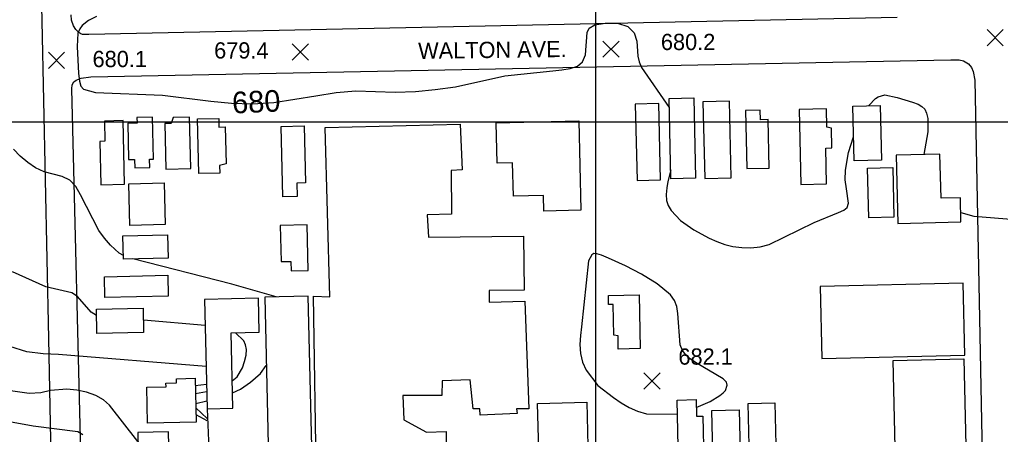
# Model space of a CAD drawing. Extents: x 79600 to 91800, y 75600 to 84400.
# Drawn here: x 81468 to 82374, y 78712 to 79095 of the extents above; entities that cross this region are included whole.
import ezdxf

# ---------------------------------------------------------------- set-up
doc = ezdxf.new("R2010")
doc.units = 0
for name, color, linetype in [('080-085$0$BLDG', 7, 'Continuous'), ('080-085$0$GRID', 7, 'Continuous'), ('080-085$0$INDEX', 7, 'Continuous'), ('080-085$0$INDXLBL', 7, 'Continuous'), ('080-085$0$INTER', 7, 'Continuous'), ('080-085$0$ROAD', 7, 'Continuous'), ('080-085$0$ROAD-NAME', 7, 'Continuous'), ('080-085$0$SPOTMARK', 7, 'Continuous'), ('080-085$0$SPOTS', 7, 'Continuous'), ('080-085$0$WALL', 7, 'Continuous')]:
    doc.layers.add(name, color=color, linetype=linetype)

# ---------------------------------------------------------------- blocks, each defined once
blk = doc.blocks.new('080-085$0$SPOTS')
at = {"layer": '080-085$0$SPOTMARK'}
for p, q in [((-0.5, -0.5), (0.5, 0.5)), ((-0.5, 0.5), (0.5, -0.5))]:
    blk.add_line(p, q, dxfattribs=at)

msp = doc.modelspace()

# ---------------------------------------------------------------- linework, layer by layer
at = {"layer": '080-085$0$BLDG'}
for points in [[(82090.51, 79022.53), (82092.23, 78948.5), (82069.5, 78947.97), (82067.78, 79022)], [(82036.53, 79016.75), (82038.17, 78946.35), (82059.99, 78946.86), (82058.36, 79017.26)], [(82099.04, 79018.93), (82100.68, 78948.3), (82125.11, 78948.87), (82123.47, 79019.5)], [(82213.18, 78943.28), (82212.42, 78976.21), (82218.08, 78976.34), (82217.65, 78994.55), (82213.4, 78995.56), (82213.01, 79012.54), (82187.74, 79011.95), (82189.35, 78942.72)], [(82238.59, 78964.59), (82237.42, 79015.04), (82262.6, 79015.62), (82263.77, 78965.18)], [(81576.7, 78999.36), (81568.13, 78999.16), (81568.91, 78965.57), (81574.34, 78965.69), (81574.52, 78958.04), (81588.4, 78958.36), (81588.22, 78965.98), (81591.91, 78966.06), (81591.01, 79004.77), (81576.58, 79004.44)], [(81608.22, 78998.95), (81602.39, 78998.81), (81603.37, 78956.86), (81626.23, 78957.39), (81625.13, 79004.7), (81610.04, 79004.35)], [(81652.1, 79003.64), (81652.28, 78995.64), (81658.12, 78995.77), (81658.91, 78961.84), (81652.82, 78960.13), (81652.99, 78953.13), (81633.8, 78952.69), (81632.63, 79003.19)], [(82159.1, 79002.61), (82152.15, 79002.45), (82151.95, 79011.15), (82138.39, 79010.84), (82139.63, 78957.32), (82160.14, 78957.79)], [(81546.5, 79001.21), (81546.93, 78982.5), (81542.32, 78982.39), (81543.25, 78942.29), (81565.1, 78942.8), (81563.73, 79001.61)], [(81730.84, 78996.65), (81732.06, 78944.04), (81724.27, 78943.86), (81724.56, 78931.47), (81711.16, 78931.16), (81709.65, 78996.16)], [(81952.12, 78918.06), (81951.79, 78932.47), (81924.11, 78931.83), (81923.39, 78962.71), (81908.97, 78962.37), (81908.11, 78999.64), (81984.31, 79001.41), (81986.23, 78918.85)], [(82336.68, 78930.36), (82318.76, 78929.94), (82317.81, 78970.71), (82277.35, 78969.77), (82278.81, 78906.67), (82337.2, 78908.03)], [(82252.13, 78911.83), (82251.06, 78957.83), (82274.18, 78958.37), (82275.25, 78912.37)], [(81570.08, 78904.84), (81569.18, 78943.29), (81601.7, 78944.05), (81602.59, 78905.6)], [(81708.93, 78904.77), (81709.71, 78871.43), (81718.78, 78871.64), (81718.99, 78862.97), (81734.65, 78863.33), (81733.68, 78905.34)], [(81605.32, 78874.69), (81564.17, 78873.73), (81563.67, 78895.25), (81604.82, 78896.2)], [(81605.54, 78839.62), (81547.08, 78838.27), (81546.63, 78857.53), (81605.09, 78858.89)], [(82208.68, 78781.92), (82340.86, 78785), (82339.32, 78851.44), (82207.14, 78848.36)], [(82020.91, 78790.72), (82020.62, 78803.02), (82016.87, 78803.68), (82016.22, 78831.96), (82011.92, 78831.86), (82011.73, 78840.05), (82040.02, 78840.7), (82041.17, 78791.19)], [(81665.19, 78736.17), (81663.58, 78805.74), (81689.45, 78806.35), (81688.72, 78837.74), (81638.93, 78836.58), (81641.27, 78735.62)], [(81734.68, 78839.52), (81694.54, 78838.59), (81698.65, 78661.69), (81738.79, 78662.62)], [(81582.78, 78806.05), (81539.68, 78805.05), (81539.16, 78827.59), (81582.25, 78828.59)], [(82274.47, 78780.31), (82339.93, 78781.83), (82342.42, 78674.58), (82276.96, 78673.06)], [(81603.44, 78755.91), (81603.36, 78759.27), (81613.12, 78759.49), (81613.03, 78763.35), (81630.31, 78763.75), (81631.25, 78723.35), (81586.41, 78722.31), (81585.64, 78755.49)], [(81946.46, 78740.52), (81991.78, 78741.57), (81993.03, 78687.64), (81947.71, 78686.59)], [(82092.68, 78744.09), (82093.04, 78728.69), (82098.82, 78728.82), (82099.8, 78686.83), (82076.46, 78686.29), (82075.12, 78743.68)], [(82165.37, 78740.96), (82166.56, 78689.53), (82141.99, 78688.95), (82140.8, 78740.39)], [(82132.43, 78734.73), (82133.64, 78682.46), (82108.46, 78681.88), (82107.25, 78734.15)], [(81577.29, 78713.71), (81578.44, 78664.11), (81606.89, 78664.77), (81605.74, 78714.37)]]:
    msp.add_lwpolyline(points, close=True, dxfattribs=at)
msp.add_lwpolyline([(81742.38, 78663.46), (81739.5, 78839.69), (81754.65, 78838.94), (81750.32, 78995.26), (81874.78, 78998.42), (81876.63, 78956.04), (81866.52, 78955.65), (81866.83, 78915.24), (81844.52, 78914.74), (81845.73, 78894.11), (81933.42, 78894.85), (81933.98, 78845.18), (81901.85, 78844.85), (81901.68, 78833.9), (81934.51, 78834.79), (81938.45, 78735.59), (81926.94, 78735.62), (81927.49, 78731.27), (81893.25, 78729.68), (81892.99, 78735.43), (81886.81, 78735.59), (81884.22, 78762.4), (81858.4, 78761.35), (81858.09, 78747.88), (81821.89, 78747.84), (81822.81, 78725.53), (81843.82, 78713.96), (81861.92, 78714.61), (81862.49, 78666.21)], dxfattribs=at)
at = {"layer": '080-085$0$GRID'}
for p, q in [((82000, 80000), (82000, 76000)), ((85000, 79000), (80000, 79000))]:
    msp.add_line(p, q, dxfattribs=at)
at = {"layer": '080-085$0$INDEX'}
for p, q in [((81630.85, 78740.46), (81641.1, 78742.95)), ((81641.53, 78726.51), (81630.95, 78736.44))]:
    msp.add_line(p, q, dxfattribs=at)
for points in [[(81539.12, 79097.8), (81531.83, 79093.98), (81526.12, 79089.4), (81523.78, 79086.42), (81522.18, 79082.37), (81521.51, 79070.03), (81522.62, 79044.95), (81523.42, 79037.98), (81524.83, 79033.31), (81527.4, 79030.51), (81538.34, 79027.64), (81600.29, 79025.07), (81644.92, 79019.65), (81663.72, 79017.64), (81683.15, 79017.22), (81702.82, 79018.35), (81741.65, 79024.35), (81760.41, 79027.56), (81778.61, 79029.17), (81814.84, 79027.92), (81833.57, 79028.36), (81852, 79030.2), (81870.52, 79032.69), (81916.24, 79043.03), (81960.4, 79047.61), (81968.87, 79048.46), (81976.61, 79049.66), (81983.12, 79051.9), (81987.85, 79055.98), (81990.47, 79062.33), (81992.06, 79082.78), (81994.02, 79086.96), (81999.31, 79089.87), (82008.81, 79091.57), (82020.06, 79091.4), (82029.76, 79088.52), (82035.44, 79082.52), (82037.86, 79074.79), (82039.03, 79061.04), (82040.03, 79055.83), (82042.25, 79050.53), (82067.97, 79013.66)], [(82252.24, 79015.38), (82258.26, 79021.88), (82260.78, 79023.67), (82266.91, 79025.24), (82278.41, 79023.05), (82292.56, 79018.62), (82297.64, 79016.67), (82301.19, 79014.66), (82303.69, 79012.05), (82305.51, 79008.39), (82306.66, 79003.63), (82306.6, 78991.08), (82302.86, 78970.36)], [(82069.31, 78956.26), (82066.76, 78945.41), (82065.59, 78939.41), (82064.96, 78933.33), (82065.34, 78927.92), (82066.85, 78923.1), (82069.54, 78918.53), (82078.34, 78909.44), (82090.61, 78900.72), (82104.65, 78893.1), (82111.79, 78889.96), (82119.09, 78887.39), (82126.75, 78885.48), (82134.9, 78884.34), (82143.36, 78884.14), (82151.84, 78885.1), (82160.14, 78887.32), (82201.62, 78907.59), (82224.23, 78916.66), (82229.09, 78918.83), (82232.12, 78921.41), (82233.29, 78925.29), (82231.39, 78938.52), (82230.39, 78947.01), (82230.6, 78955.98), (82233.37, 78972.22), (82238.08, 78986.63)], [(82337, 78916.64), (82348.93, 78913.54), (82398.5, 78909.24), (82416.01, 78908.45), (82456.76, 78912.78), (82495.76, 78914.01), (82513.74, 78915.35), (82523.1, 78916.77), (82532.3, 78919), (82549.37, 78926.02), (82577.6, 78942.02), (82591.27, 78948.92), (82632.69, 78962.68), (82659.92, 78974.09), (82680.21, 78978.89)], [(81564.09, 78877.11), (81560.05, 78879.25), (81552.13, 78886.72), (81546.7, 78892.95), (81541.27, 78900.19), (81524.57, 78933.04), (81520.29, 78940.67), (81514.77, 78946.48), (81507.58, 78949.89), (81490.92, 78954.29), (81483.04, 78957.97), (81475.75, 78962.94), (81468.93, 78968.77), (81462.51, 78975.14)], [(81704.96, 78838.83), (81664.07, 78850.77), (81572.82, 78873.93)], [(81664.86, 78750.31), (81672.28, 78753.84), (81681.49, 78760.24), (81690.52, 78768.21), (81696, 78775.49)]]:
    msp.add_lwpolyline(points, dxfattribs=at)
at = {"layer": '080-085$0$INTER'}
for p, q in [((81639.49, 78812.46), (81582.51, 78817.43)), ((81630.47, 78757.22), (81640.74, 78758.36)), ((81630.64, 78749.7), (81640.9, 78751.57)), ((81631.09, 78730.42), (81641.1, 78724.79))]:
    msp.add_line(p, q, dxfattribs=at)
for points in [[(82092.85, 78736.67), (82105.64, 78742.37), (82114.62, 78747.72), (82117.71, 78750.21), (82119.73, 78752.54), (82121.46, 78757.3), (82120.66, 78760.05), (82117.76, 78763.24), (82092.18, 78778.28), (82087.18, 78781.65), (82083.18, 78785.25), (82080.11, 78789.43), (82077.95, 78794.48), (82075.83, 78823.6), (82074.85, 78830.01), (82072.71, 78835.56), (82068.98, 78840.71), (82056.63, 78850.86), (82042.25, 78859.72), (82027.6, 78867.4), (82011.91, 78874.76), (82005.52, 78877.4), (82001.18, 78878.74), (81998.42, 78878.78), (81996.49, 78877.63), (81993.33, 78872.05), (81986.82, 78811.29), (81985.95, 78803.26), (81985.5, 78794.93), (81985.94, 78786.57), (81987.82, 78778.51), (81991.37, 78771.13), (82002.07, 78757.04)], [(81539.29, 78821.79), (81534.37, 78824.82), (81521.62, 78839.14), (81516.52, 78842.6), (81492.49, 78848.14), (81461.59, 78861.87)], [(81664.61, 78761.26), (81669.14, 78765.08), (81673.89, 78773.37), (81676.01, 78779.21), (81677.38, 78785.08), (81677.64, 78790.25), (81676.89, 78794.61), (81675.29, 78798.22), (81667.46, 78805.83)], [(81640.36, 78774.72), (81504.27, 78785.74), (81490.01, 78786.18), (81475.02, 78788.31), (81459.26, 78793.06)], [(81577.48, 78705.4), (81551.37, 78738.85), (81545.83, 78743.8), (81538.6, 78747.89), (81530.1, 78750.98), (81520.99, 78752.93), (81511.94, 78753.67), (81496.87, 78752.59), (81487.89, 78750.3), (81477.18, 78749.67), (81403.53, 78760.14)], [(82002.07, 78757.04), (82016.49, 78746.01), (82023.59, 78741.15), (82030.95, 78736.8), (82038.64, 78733.34), (82046.88, 78731.02), (82075.43, 78730.6)], [(81526.75, 78711.46), (81522.15, 78714.26), (81480.69, 78719.67), (81428.46, 78728.99), (81391.62, 78734.22), (81314.06, 78742.86), (81292.16, 78744.88), (81270.2, 78746.03), (81253.4, 78746.21), (81236.04, 78744.25), (81132.66, 78714.51), (81099.62, 78705.21)]]:
    msp.add_lwpolyline(points, dxfattribs=at)
at = {"layer": '080-085$0$ROAD'}
for points in [[(81470.24, 79910.91), (81477.57, 79602.01), (81488.86, 79093.38), (81495.04, 78800.43), (81496.52, 78722.16), (81497.71, 78662.31)], [(82278.29, 79096.63), (81532.24, 79081.17), (81526.21, 79081.05), (81524.67, 79081.61), (81522.85, 79082.88), (81520.19, 79085.7), (81517.95, 79089.21), (81516.14, 79094.27), (81515.88, 79099.32)], [(81525.34, 78670.94), (81516.53, 79030.99), (81516.68, 79034.63), (81518.37, 79037.44), (81520.62, 79038.97), (81524.97, 79040.64), (81533.96, 79042.02), (82327.71, 79057.76), (82335.43, 79057.74), (82339.64, 79056.75), (82344.12, 79053.93), (82346.92, 79050.55), (82348.45, 79046.9), (82349.97, 79039.04), (82356.96, 78677.31)]]:
    msp.add_lwpolyline(points, dxfattribs=at)
at = {"layer": '080-085$0$WALL'}
msp.add_line((81641.49, 78735.48), (81644.26, 78663.32), dxfattribs=at)

# ---------------------------------------------------------------- block references
at = {"layer": '080-085$0$SPOTMARK', "xscale": 15, "yscale": 15}
for p in [(82368.71, 79078.08), (82014.19, 79067.55), (81727.33, 79065.01), (81502.37, 79057.11), (82051.96, 78761.33)]:
    msp.add_blockref('080-085$0$SPOTS', p, dxfattribs=at)

# ---------------------------------------------------------------- texts
at = {"layer": '080-085$0$INDXLBL'}
msp.add_text('680', height=20, rotation=2.57071, dxfattribs=at).set_placement((81664.84, 79008.07))
at = {"layer": '080-085$0$ROAD-NAME'}
msp.add_text('WALTON AVE.', height=15, rotation=0.74364, dxfattribs=at).set_placement((81836.24, 79058.51))
at = {"layer": '080-085$0$SPOTS'}
for s, p in [('680.2', (82060.22, 79066.69)), ('680.1', (81535.61, 79050.96)), ('679.4', (81647.85, 79058.87)), ('682.1', (82076.38, 78776.33))]:
    msp.add_text(s, height=15, dxfattribs=at).set_placement(p)

doc.saveas('drawing.dxf')
